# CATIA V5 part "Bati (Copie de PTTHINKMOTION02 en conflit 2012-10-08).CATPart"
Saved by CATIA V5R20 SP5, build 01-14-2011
Part number: Bati
Bounding box of the stored display mesh (mm): x -250 to 20, y -10 to 10, z -15 to 130
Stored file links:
  E:\IAO_2010\iao\IAO_MMS_Groupe2\IAO_MMS_Groupe2\melguidj\Catia\Bati.CATPart
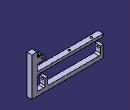
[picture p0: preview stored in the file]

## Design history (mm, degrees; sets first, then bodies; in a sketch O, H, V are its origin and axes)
Body1 (main body)
  Plane1: stored without definition
  Sketch1 on zx-plane, origin (0, 0, 0), H (-1, 0, 0), V (0, 0, 1)
    line L1 (0, 130) -> (-20, 130)
    point P1 (0, 130)
    line L2 (-20, 130) -> (-20, -15)
    line L3 (-20, -15) -> (250, -15)
    point P4 (250, -15)
    line L4 (0, 130) -> (0, 115)
    line L5 (5, 0) -> (25, 0)
    line L6 (30, 5) -> (30, 30)
    line L7 (30, 30) -> (40, 30)
    line L8 (40, 30) -> (40, 5)
    point P7 (40, 0)
    line L9 (45, 0) -> (235, 0)
    line L10 (240, 5) -> (240, 30)
    point P8 (240, 30)
    line L11 (240, 30) -> (250, 30)
    line L12 (250, 30) -> (250, -15)
    point P10 (250, -15)
    reference intersected line E1 through (0, 0) direction (-1, 0) from Plane1
    point P11 (0, 110)
    line L13 (5, 110) -> (20, 110)
    line L14 (20, 90) -> (5, 90)
    line L15 (0, 85) -> (0, 70)
    circle A1 centre (20, 100) radius 4
    point P12 (20, 100)
    arc A2 centre (45, 5) radius 5 from (40, 5) to (45, 0) ccw
    arc A3 centre (25, 5) radius 5 from (30, 5) to (25, 0) cw
    arc A4 centre (5, 5) radius 5 from (5, 0) to (0, 5) cw
    arc A5 centre (235, 5) radius 5 from (240, 5) to (235, 0) cw
    arc A6 centre (5, 85) radius 5 from (5, 90) to (0, 85) ccw
    arc A7 centre (5, 115) radius 5 from (5, 110) to (0, 115) cw
    line L16 (5, 65) -> (250, 65)
    line L17 (250, 65) -> (250, 55)
    line L18 (250, 55) -> (5, 55)
    line L19 (0, 50) -> (0, 5)
    arc A8 centre (5, 50) radius 5 from (0, 50) to (5, 55) cw
    arc A9 centre (5, 70) radius 5 from (5, 65) to (0, 70) cw
    arc A10 centre (20, 100) radius 10 from (20, 90) to (20, 110) ccw
    distance L9 L3 = 15
    distance L10 L12 = 10
    length L7 = 10
    distance L8 L10 = 200
    distance L6 L4 = 30
    length L1 = 20
    distance L1 E1 = 130
    distance L14 L5 = 90
    distance P12 L13 = 10
    radius A1 = 4
    distance L7 L9 = 30
    radius A2 = 5
    radius A3 = 5
    radius A4 = 5
    radius A5 = 5
    radius A6 = 5
    radius A7 = 5
    length L17 = 10
    distance L18 L5 = 55
    radius A8 = 5
    radius A9 = 5
    distance P12 L4 = 20
    coincidence: P1 V, P7 L5, P8 L7, P10 P4, L5 H, L4 L15, L8 P7, L9 P7, L13 P11, L4 P11, L17 L12, L15 L19
    horizontal: L1 H, L3 H, L5 H, L7 H, L9 H, L11 H, L13 H, L14 H, L16 H, L18 H
    vertical: L2 V, L4 V, L6 V, L8 V, L10 V, L12 V, L15 V, L17 V, L19 V
    tangency: A2 L8, A2 L9, A3 L6, A3 L5, A4 L5, A4 L15, A5 L10, A5 L9, A6 L14, A6 L15, A7 L13, A7 L4, A8 L19, A8 L18, A9 L16, A9 L15, A10 L13, A10 L14
  Pad1: profile Sketch1, direction (0, 1, 0), length 10, mirrored extent
  Sketch2 on face of Pad1 from Sketch1.L12, origin (-250, 0, 0), H (0, -1, 0), V (0, 0, 1)
    circle A1 centre (0, 23) radius 4
    point P1 (0, 23)
    reference projected line E1 (10, 30) -> (-10, 30) from edge [face of Pad1 from Sketch1.L11 | face of Pad1 from Sketch1.L12]
    radius A1 = 4
    distance E1 P1 = 7
    coincidence: P1 V
  Pocket1: profile Sketch2, direction (1, 0, 0), up to face of Pad1 from Sketch1.L6
  Sketch3 on face of Pad1 from Sketch1.L13, origin (0, 0, 110), H (1, 0, 0), V (0, 1, 0)
    line L1 (-53.7186, 7) -> (-5, 7)
    line L2 (-5, 7) -> (-5, -7)
    line L3 (-5, -7) -> (-53.7186, -7)
    line L4 (-53.7186, -7) -> (-53.7186, 7)
    reference projected line E1 (-20, 10) -> (-5, 10) from edge [face of Pad1 from Sketch1.L13 | end face of Pad1]
    reference projected line E2 (-20, -10) -> (-5, -10) from edge [start face of Pad1 | face of Pad1 from Sketch1.L13]
    reference projected line E3 (-5, -10) -> (-5, 10) from edge [face of Pad1 from Sketch1.A7 | face of Pad1 from Sketch1.L13]
    distance L1 E1 = 3
    distance L3 E2 = 3
    horizontal: L1 H, L3 H
    vertical: L2 V, L4 V
    coincidence: L2 E3
  Pocket2: profile Sketch3, direction (0, 0, -1), up to face of Pad1 from Sketch1.L14
  Sketch4 on face of Pad1 from Sketch1.L16, origin (0, 0, 65), H (1, 0, 0), V (0, 1, 0)
    circle A1 centre (-215, 0) radius 4
    point P1 (-215, 0)
    reference projected line E1 (-250, -10) -> (-250, 10) from edge [face of Pad1 from Sketch1.L16 | face of Pad1 from Sketch1.L17]
    radius A1 = 4
    distance P1 E1 = 35
    coincidence: P1 H
  Pocket3: profile Sketch4, direction (0, 0, -1), through (limit type 6)
  Sketch5 on zx-plane, origin (0, 0, 0), H (-1, 0, 0), V (0, 0, 1)
    point P1 (20, 100)
    reference projected arc E1 centre (20, 100) radius 10 from (20, 90) to (20, 110) ccw from edge [face of Pad1 from Sketch1.A10 | end face of Pad1]
    concentricity: E1 P1
  Sketch6 on face of Pad1 from Sketch1.L16, origin (-109.5895, -1.7809, 65), H (1, 0, 0), V (0, 1, 0)
    point P1 (-21.9505, 1.7809)
    reference projected circle E1 centre (-105.4105, 1.7809) radius 4 from edge [face of Pad1 from Sketch1.L16 | face of Pocket3 from Sketch4.A1]
    reference projected line E2 (-140.4105, 11.7809) -> (104.5895, 11.7809) from edge [face of Pad1 from Sketch1.L16 | end face of Pad1]
    distance P1 E1 = 79.46
    distance P1 E2 = 10
  Hole1: placed by Sketch6, at (-131.54, 0, 65) direction (0, 0, -1), diameter 8, through (limit type 6)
